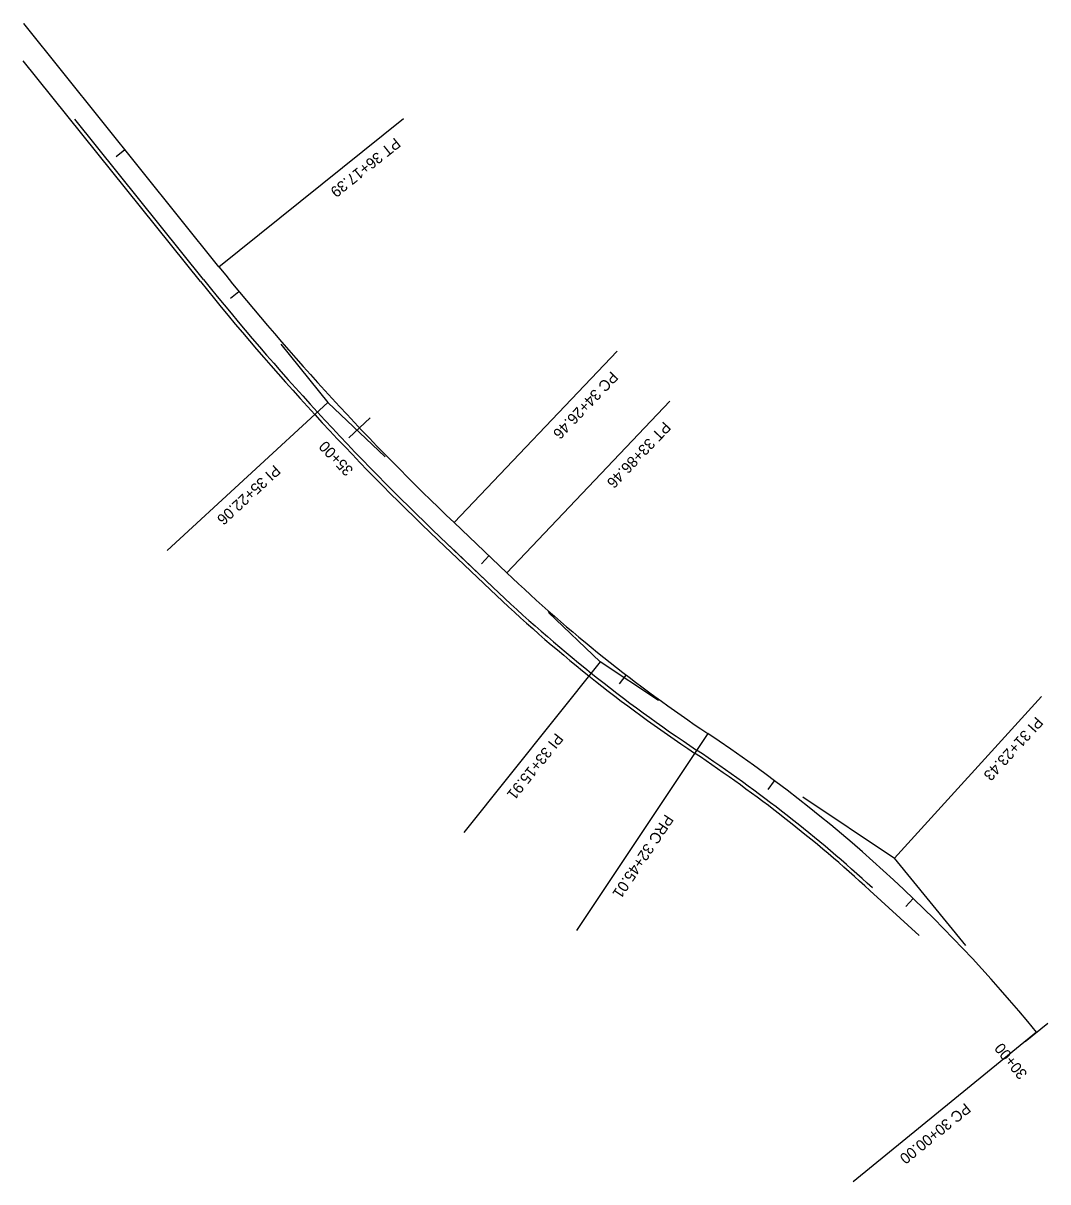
# Model space of a CAD drawing. Extents: x 955367 to 987800, y 1869413 to 1923417.
# Drawn here: x 955367 to 955930, y 1922780 to 1923417 of the extents above; entities that cross this region are included whole.
import ezdxf

# ---------------------------------------------------------------- set-up
doc = ezdxf.new("R2010")
doc.units = 0
for name, color, linetype in [('R_Horz Alg', 7, 'Continuous'), ('R_Horz Alg Annot', 7, 'Continuous'), ('R_Proposed Road', 7, 'Continuous')]:
    doc.layers.add(name, color=color, linetype=linetype)

msp = doc.modelspace()

# ---------------------------------------------------------------- linework, layer by layer
at = {"layer": 'R_Horz Alg'}
for p, q in [((955474.39, 1923282.9), (955367.11, 1923416.43)), ((955465.81, 1923276.01), (955395.17, 1923363.94)), ((955632.49, 1923114.87), (955603.52, 1923142.44)), ((955624.91, 1923106.9), (955595.94, 1923134.48)), ((955624.91, 1923106.9), (955601.25, 1923129.42))]:
    msp.add_line(p, q, dxfattribs=at)
for centre, radius, start, end in [((956591.07, 1924179.99), 1432.39, 218.7769, 226.41419), ((956591.07, 1924179.99), 1443.39, 218.7769, 226.41419), ((956196.81, 1923707.75), 818.51, 226.41419, 236.31552), ((956196.81, 1923707.75), 829.51, 226.41419, 236.31552), ((955288.89, 1922345.58), 818.51, 39.16489, 56.31552), ((955288.89, 1922345.58), 807.51, 47.60349, 56.31552)]:
    msp.add_arc(centre, radius, start, end, dxfattribs=at)
at = {"layer": 'R_Horz Alg Annot'}
for p, q in [((955508.44, 1923240.51), (955534.27, 1923208.36)), ((955565.65, 1923178.49), (955534.27, 1923208.36)), ((955655.34, 1923093.12), (955683.85, 1923065.99)), ((955715.84, 1923044.67), (955683.85, 1923065.99)), ((955795.13, 1922991.82), (955845.55, 1922958.21)), ((955884.67, 1922910.18), (955845.55, 1922958.21))]:
    msp.add_line(p, q, dxfattribs=at)
for points in [[(955474.39, 1923282.9), (955575.74, 1923364.31)], [(955417.97, 1923343.54), (955422.65, 1923347.3)], [(955480.73, 1923265.59), (955485.36, 1923269.41)], [(955603.52, 1923142.44), (955693.15, 1923236.61)], [(955534.27, 1923208.36), (955445.93, 1923127.14)], [(955632.49, 1923114.87), (955722.12, 1923209.03)], [(955545.77, 1923188.99), (955557.38, 1923200)], [(955618.55, 1923119.86), (955622.68, 1923124.2)], [(955683.85, 1923065.99), (955608.93, 1922972.25)], [(955694.49, 1923053.92), (955698.15, 1923058.68)], [(955845.55, 1922958.21), (955926.25, 1923047.02)], [(955742.85, 1923026.66), (955670.75, 1922918.49)], [(955776, 1922995.88), (955779.59, 1923000.68)], [(955851.62, 1922931.67), (955855.77, 1922936)], [(955917.3, 1922857.46), (955929.71, 1922867.56)], [(955923.5, 1922862.51), (955822.71, 1922780.41)]]:
    msp.add_lwpolyline(points, dxfattribs=at)
at = {"layer": 'R_Proposed Road'}
for p, q in [((955464.26, 1923274.75), (955366.82, 1923396.03)), ((955623.53, 1923105.45), (955594.56, 1923133.03)), ((955859.07, 1922915.74), (955832.01, 1922940.44))]:
    msp.add_line(p, q, dxfattribs=at)
for centre, radius, start, end in [((956591.07, 1924179.99), 1445.39, 218.7769, 226.41419), ((956196.81, 1923707.75), 831.51, 226.41419, 236.31552), ((955288.89, 1922345.58), 805.51, 47.60349, 56.31552)]:
    msp.add_arc(centre, radius, start, end, dxfattribs=at)

# ---------------------------------------------------------------- texts
at = {"layer": 'R_Horz Alg'}
for rotation, p in [(128.7769, (955367.77, 1923416.41)), (128.7769, (955475.05, 1923282.87)), (136.41419, (955604.18, 1923142.51)), (136.41419, (955633.15, 1923114.93)), (146.31552, (955743.48, 1923026.84)), (129.16489, (955924.16, 1922862.49))]:
    msp.add_text('+', height=1, rotation=rotation, dxfattribs=at).set_placement(p)
at = {"layer": 'R_Horz Alg Annot'}
for s, rotation, p in [('PT 36+17.39', 218.7769, (955571.07, 1923354.15)), ('PC 34+26.46', 226.41419, (955689.88, 1923225.92)), ('PT 33+86.46', 226.41419, (955718.85, 1923198.34)), ('35+00', 133.47246, (955548.59, 1923171.48)), ('PI 35+22.06', 222.59555, (955504.8, 1923174.48)), ('PI 31+23.43', 227.74021, (955923.23, 1923036.26)), ('PI 33+15.91', 231.36486, (955659.35, 1923027.32)), ('PRC 32+45.01', 236.31552, (955719.55, 1922982.7)), ('30+00', 129.16489, (955918.8, 1922839.79)), ('PC 30+00.00', 219.16489, (955884.24, 1922824.08))]:
    msp.add_text(s, height=6, rotation=rotation, dxfattribs=at).set_placement(p)

doc.saveas('drawing.dxf')
